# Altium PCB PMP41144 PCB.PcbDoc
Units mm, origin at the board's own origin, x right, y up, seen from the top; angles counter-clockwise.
Board outline 56.79 x 28.91 mm, 6 copper layers (Top Layer 1, Layer 1, Top Layer, Bottom Layer, Layer 2, Bottom Layer 1), stack 1.025 mm thick; 53 components, 24 nets, 115 pads, 67 vias.
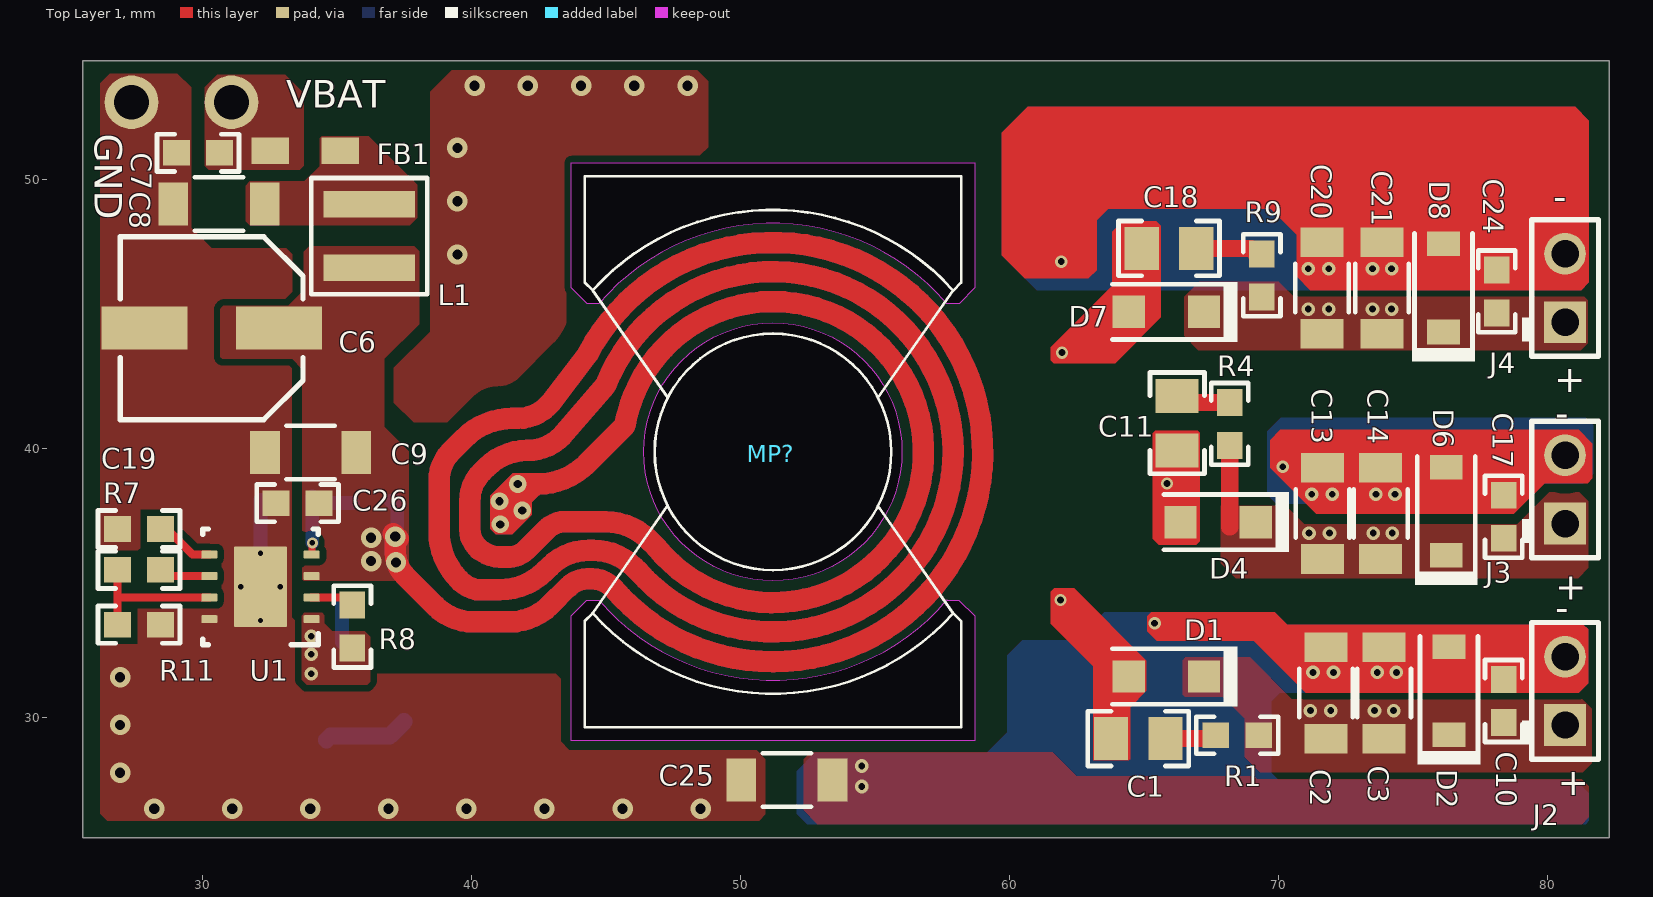
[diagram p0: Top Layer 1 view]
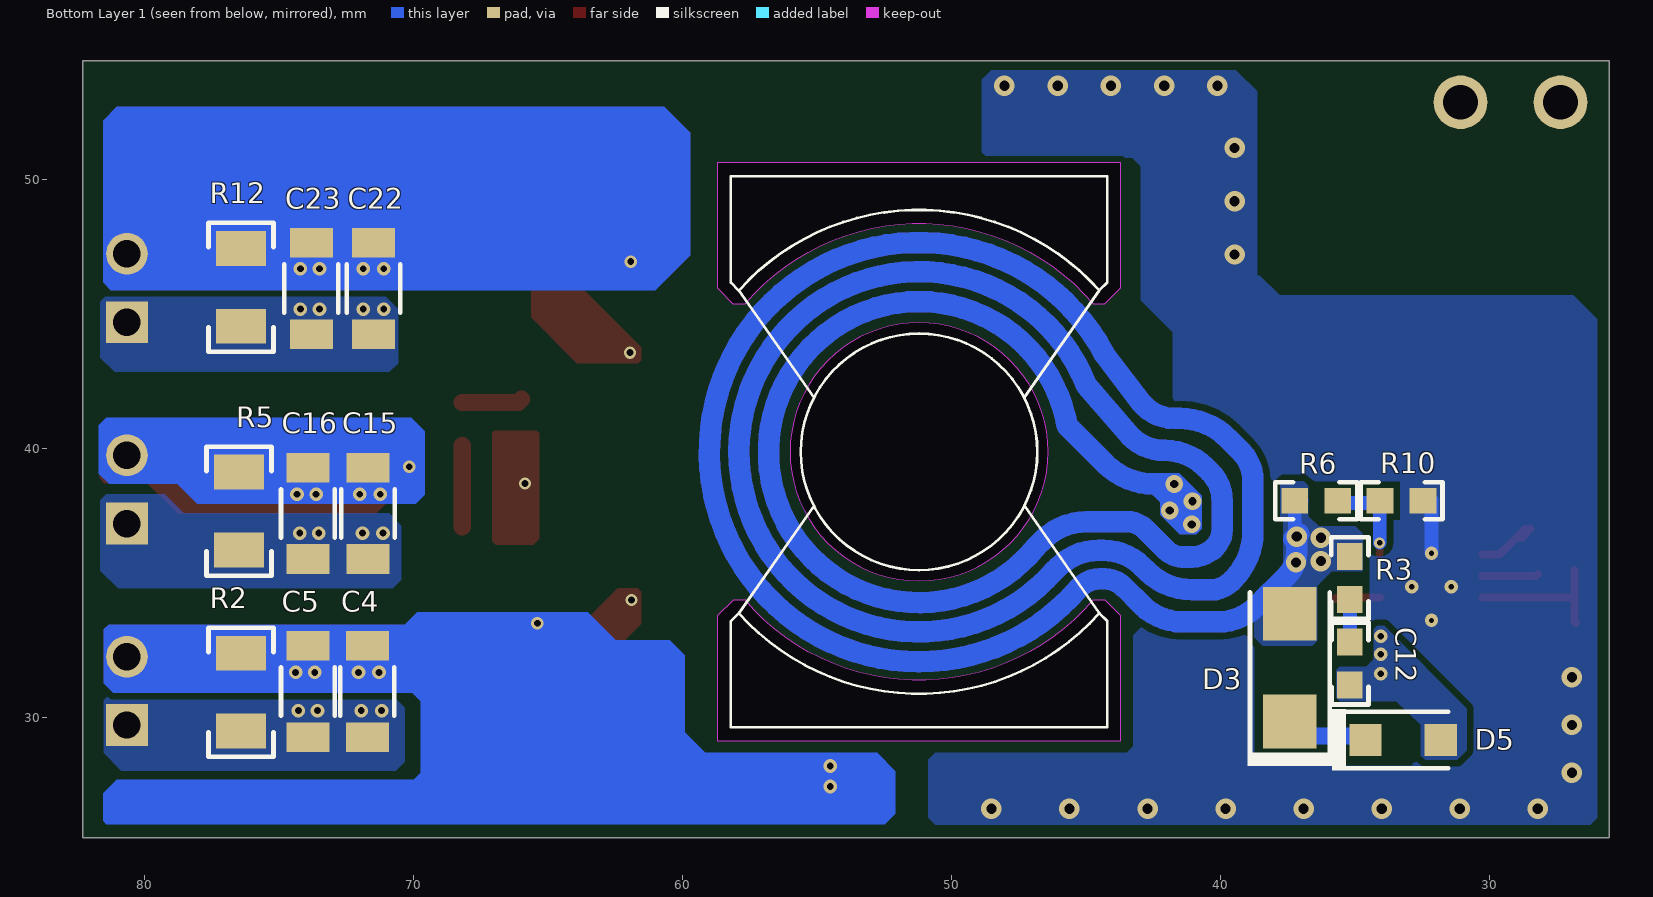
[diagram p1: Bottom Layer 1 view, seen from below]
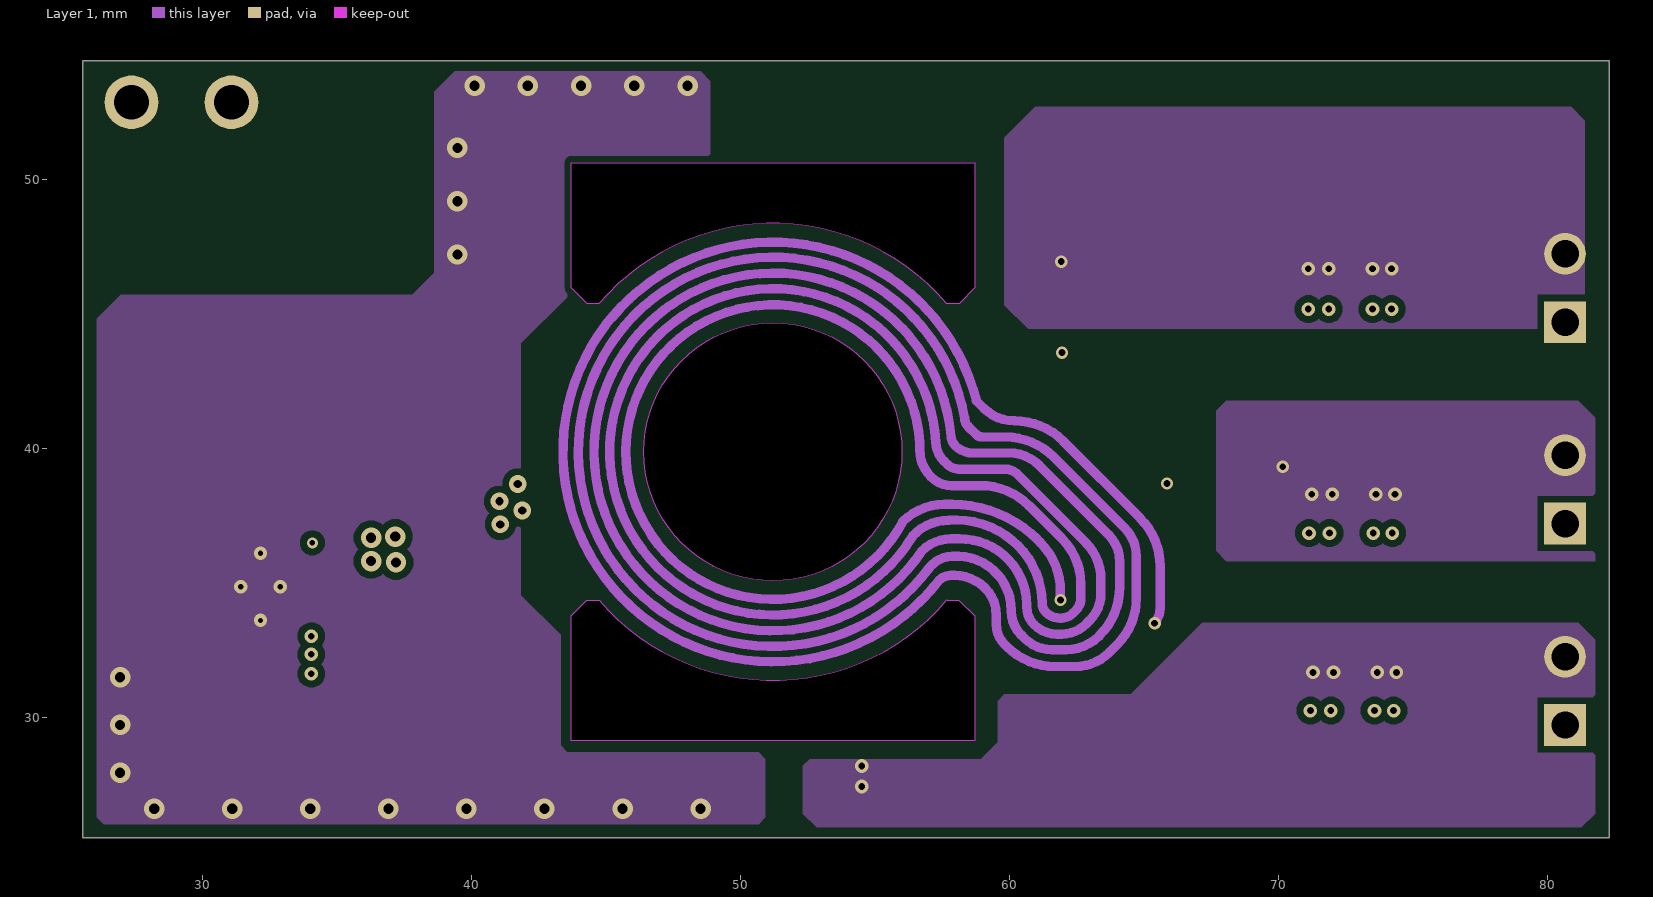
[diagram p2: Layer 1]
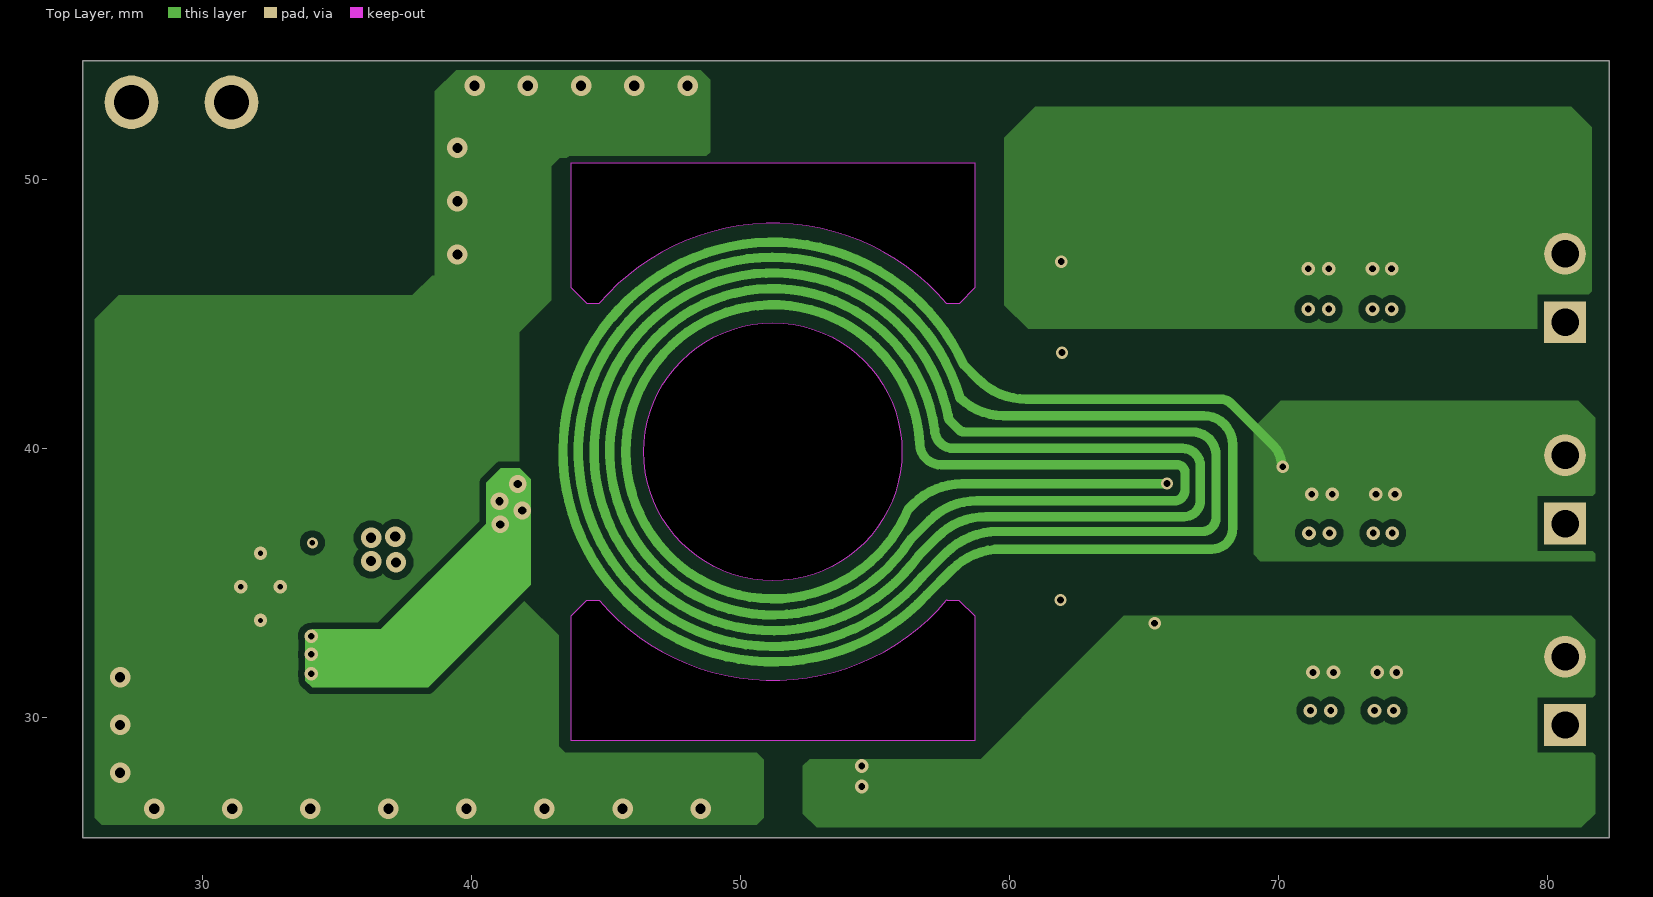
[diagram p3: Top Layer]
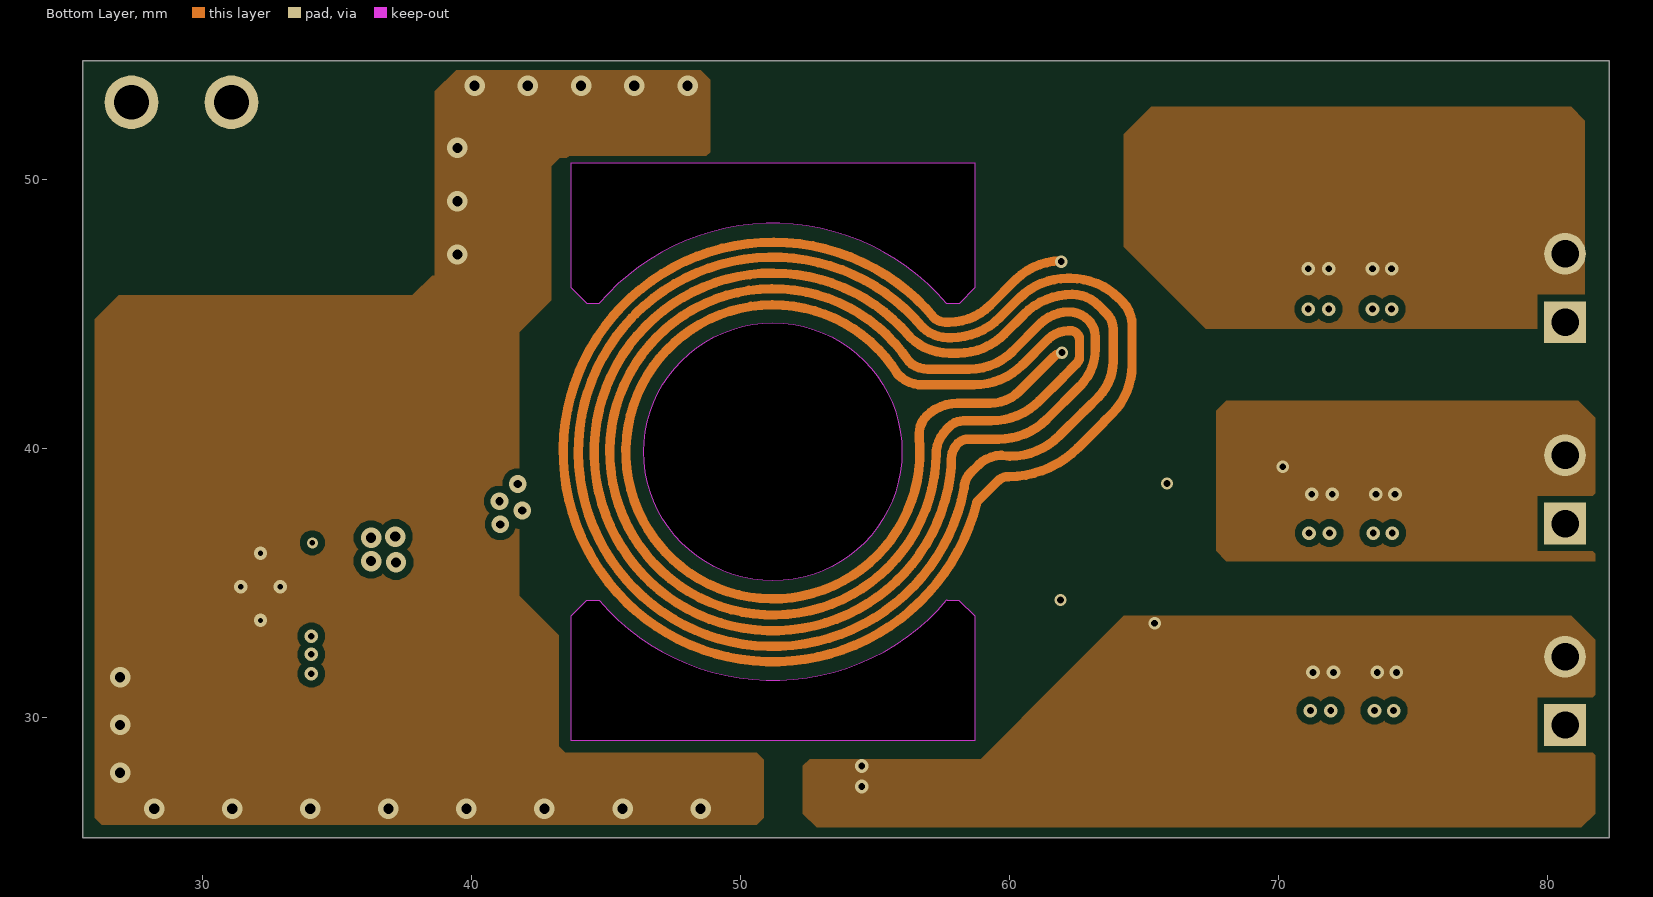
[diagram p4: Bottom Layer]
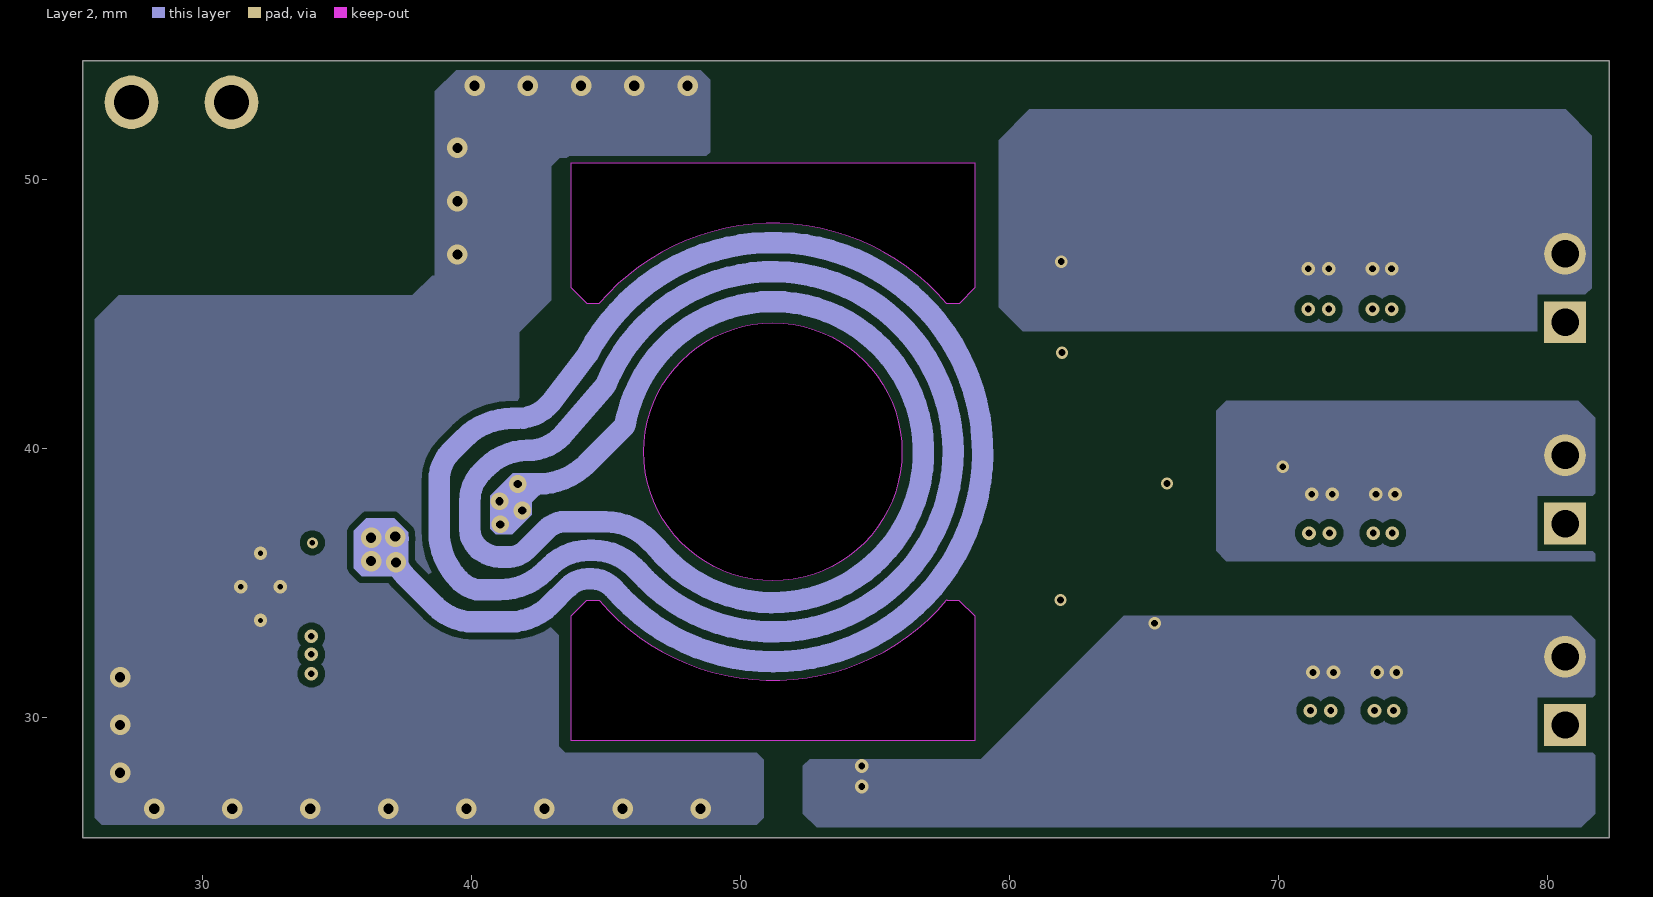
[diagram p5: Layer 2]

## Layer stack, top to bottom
Top Solder: solder mask 0.0102, Solder Resist, Dk 3.5
Top Layer 1: signal copper 0.07
Dielectric 2: prepreg 0.0711, PP-006, Dk 4.1
Layer 1: signal copper 0.07
Dielectric 3: prepreg 0.0711, PP-006, Dk 4.1
Top Layer: signal copper 0.07
Dielectric 1: dielectric 0.32, FR-4, Dk 4.8
Bottom Layer: signal copper 0.07
Dielectric 4: prepreg 0.0711, PP-006, Dk 4.1
Layer 2: signal copper 0.07
Dielectric 5: prepreg 0.0711, PP-006, Dk 4.1
Bottom Layer 1: signal copper 0.07
Bottom Solder: solder mask 0.0102, Solder Resist, Dk 3.5

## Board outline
25.527,25.527 82.321,25.527 82.321,54.432 25.527,54.432
cut-out: 43.706,29.128 43.706,33.778 44.29,34.364 44.298,34.366 44.729,34.366 44.74,34.361 ccw(c51.206,39.878) 57.68,34.369 57.683,34.366 58.115,34.366 58.706,33.778 58.706,29.128
cut-out: 51.206,35.078 cw(c51.206,39.878) 46.406,39.878 cw(c51.206,39.878) 51.206,44.678 cw(c51.206,39.878) 56.006,39.878 cw(c51.206,39.878)
cut-out: 43.706,29.128 43.706,33.778 44.29,34.364 44.298,34.366 44.729,34.366 44.74,34.361 ccw(c51.206,39.878) 57.68,34.369 57.683,34.366 58.115,34.366 58.706,33.778 58.706,29.128
cut-out: 51.206,35.078 cw(c51.206,39.878) 46.406,39.878 cw(c51.206,39.878) 51.206,44.678 cw(c51.206,39.878) 56.006,39.878 cw(c51.206,39.878)
cut-out: 51.206,35.078 cw(c51.206,39.878) 46.406,39.878 cw(c51.206,39.878) 51.206,44.678 cw(c51.206,39.878) 56.006,39.878 cw(c51.206,39.878)
cut-out: 43.706,29.128 43.706,33.778 44.29,34.364 44.298,34.366 44.729,34.366 44.74,34.361 ccw(c51.206,39.878) 57.68,34.369 57.683,34.366 58.115,34.366 58.706,33.778 58.706,29.128
cut-out: 44.298,45.392 43.706,45.978 43.706,50.628 58.706,50.628 58.706,45.978 58.13,45.392 58.115,45.39 57.683,45.39 57.678,45.389 ccw(c51.206,39.878) 44.736,45.39 44.729,45.39

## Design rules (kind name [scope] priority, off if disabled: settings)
AcuteAngle [All] p1: minimum=4.50000000000000E+0001 checktracksonly=FALSE
AssemblyTestPointUsage [All] p1: valid=2
Clearance Clearance_BoardEdge_MountingHoles [OnCopper and InComponentClass('Mounting Holes') vs IsKeepOut] p1: gap=1.016 ignorepadtopadclearanceinfootprint=FALSE except(0: Arc-Hole Track-Hole SMDPad-Hole THPad-Hole Via-Hole Fill-Hole Poly-Hole Region-Hole Text-Hole)
Clearance Clearance_BoardEdge_Poly [OnCopper and InPoly vs IsKeepOut] p2: gap=0.635 ignorepadtopadclearanceinfootprint=FALSE except(0: Arc-Hole Track-Hole SMDPad-Hole THPad-Hole Via-Hole Fill-Hole Poly-Hole Region-Hole Text-Hole)
Clearance Clearance_BoardEdge [OnCopper and Not InComponentClass('Logo') and not InComponentClass('FiducialMark') and not InRegion(1000,500,4000,800) and Not IsKeepout vs IsKeepOut] p3: gap=0.127 ignorepadtopadclearanceinfootprint=FALSE except(0: Arc-Hole Track-Hole SMDPad-Hole THPad-Hole Via-Hole Fill-Hole Poly-Hole Region-Hole Text-Hole)
Clearance Clearance_Poly [InPolygon] p4: gap=0.254 ignorepadtopadclearanceinfootprint=FALSE except(0: Arc-Hole Track-Hole SMDPad-Hole THPad-Hole Via-Hole Fill-Hole Poly-Hole Region-Hole Text-Hole)
Clearance [All] p5: gap=0.203 ignorepadtopadclearanceinfootprint=FALSE except(0: Arc-Hole Track-Hole SMDPad-Hole THPad-Hole Via-Hole Fill-Hole Poly-Hole Region-Hole Text-Hole)
ComponentClearance ComponentClearance_Logo [All] p1: gap=0.254 collisioncheckmode=3 verticalgap=0.254 showdistances=TRUE
ComponentClearance ComponentClearance_ScrewToNut [(HasFootprint('NY PMS 440 0025 PH')) vs (HasFootprint('Keystone_1902C'))] p2: gap=0.127 collisioncheckmode=3 verticalgap=0.254 showdistances=FALSE
ComponentClearance ComponentClearance_MountingHoles [InComponentClass('Mounting Holes')] p3: gap=0.254 collisioncheckmode=3 verticalgap=2540 showdistances=FALSE
ComponentClearance ComponentClearance_SmallPassives [HasFootprint('0201*') or HasFootprint('0402*') or HasFootprint('0508') or HasFootprint('0603*') or HasFootprint('0612') or HasFootprint('0805*') or HasFootprint('0815*') or HasFootprint('0830*') or HasFootprint('1206*') or HasFootprint('1210*') or HasFootprint('1808*') or HasFootprint('1812*') or HasFootprint('1825*') or HasFootprint('2010*') or HasFootprint('2220*') or HasFootprint('2225*') or HasFootprint('2512*') or HasFootprint('2728*') or HasFootprint('3518*') vs HasFootprint('0201*') or HasFootprint('0402*') or HasFootprint('0508') or HasFootprint('0603*') or HasFootprint('0612') or HasFootprint('0805*') or HasFootprint('0815*') or HasFootprint('0830*') or HasFootprint('1206*') or HasFootprint('1210*') or HasFootprint('1808*') or HasFootprint('1812*') or HasFootprint('1825*') or HasFootprint('2010*') or HasFootprint('2220*') or HasFootprint('2225*') or HasFootprint('2512*') or HasFootprint('2728*') or HasFootprint('3518*')] p4: gap=0.254 collisioncheckmode=3 verticalgap=0.254 showdistances=FALSE
ComponentClearance ComponentClearance_THtoSMT [IsThruComponent vs IsSMTComponent] p5: gap=0.254 collisioncheckmode=3 verticalgap=2540 showdistances=FALSE
ComponentClearance ComponentClearance_THtoTH [IsThruComponent vs IsThruComponent] p6: gap=0.254 collisioncheckmode=3 verticalgap=2540 showdistances=FALSE
ComponentClearance [All] p7: gap=0.254 collisioncheckmode=3 verticalgap=0.254 showdistances=FALSE
DiffPairsRouting [All] p1: maxlimit=2.54 minlimit=0.254 mostfreqgap=0.254 toplayer_minwidth=0.381 toplayer_maxwidth=0.381 toplayer_prefwidth=0.381 midlayer1_minwidth=0.381 midlayer1_maxwidth=0.381 midlayer1_prefwidth=0.381 midlayer2_minwidth=0.381 midlayer2_maxwidth=0.381 midlayer2_prefwidth=0.381 midlayer3_minwidth=0.381 midlayer3_maxwidth=0.381 midlayer3_prefwidth=0.381 midlayer4_minwidth=0.381 midlayer4_maxwidth=0.381 midlayer4_prefwidth=0.381 bottomlayer_minwidth=0.381 bottomlayer_maxwidth=0.381 bottomlayer_prefwidth=0.381 maxuncoupledlength=25.4
FabricationTestPointUsage TestPointUsage [All] p1: valid=2 allowmultiple=FALSE
FabricationTestpoint Testpoint [All] p1: side=3 testpointundercomponent=TRUE minsize=1.016 maxsize=2.54 preferedsize=1.524 minholesize=0 maxholesize=1.016 preferedholesize=0.813 testpointgrid=0.025 allowsidetop=TRUE allowsidebottom=TRUE usegrid=TRUE gridtolerance=0
FanoutControl Fanout_LCC [IsLCC] p1: bgadir=Out bgaviamode=Centered fanoutstyle=Auto fanoutdirection=Alternating viagrid=0.025 // Fanout_LCC (Default Rule)
FanoutControl Fanout_BGA [IsBGA] p2: bgadir=Out bgaviamode=Centered fanoutstyle=Auto fanoutdirection=Alternating viagrid=0.025 // Fanout_BGA (Default Rule)
FanoutControl Fanout_Default [All] p4: bgadir=Out bgaviamode=Centered fanoutstyle=Auto fanoutdirection=Alternating viagrid=0.025 // Fanout_Default (Default Rule)
FanoutControl Fanout_Small [(CompPinCount < 5)] p5: bgadir=Out bgaviamode=Centered fanoutstyle=Auto fanoutdirection=OutThenIn viagrid=0.025 // Fanout_Small (Default Rule)
HoleSize [All] p1: absolutevalues=TRUE maxlimit=6.375 minlimit=0.152 maxpercent=80.000 minpercent=20.000
MinimumAnnularRing [All] p1: minimumring=0.076
MinimumSolderMaskSliver MinimumSolderMaskSliver_Logo [InComponentClass('Logo') vs InComponentClass('Logo')] p1: minsoldermaskwidth=0.018
MinimumSolderMaskSliver [All] p2: minsoldermaskwidth=0
PlaneConnect [All] p1: planeconnectstyle=Direct reliefexpansion=0.254 reliefentries=4 reliefconductorwidth=0.254 reliefairgap=0.254
PolygonConnect [All] p1: connectstyle=Direct reliefconductorwidth=0.254 reliefentries=4 polygonreliefangle="90 Angle" airgapwidth=0.254
RoutingCorners [All] p1: cornerstyle=45-Degree minsetback=0.254 maxsetback=2.54
RoutingVias [All] p1: holewidth=0.406 width=0.864 viastyle="Through Hole" minholewidth=0.203 minwidth=0.406 maxholewidth=1.016 maxwidth=1.651
SMDToCorner [All] p1: distance=0
SilkToSilkClearance [All] p1: silktosilkclearance=0
SilkToSolderMaskClearance SilkscreenOverComponentPads [IsPad] p1: minsilkscreentomaskgap=0 clearancetoexposedcopper=TRUE
SolderMaskExpansion [All] p1: expansion=0.076 istentingtop=FALSE
Width [All] p1: maxlimit=2.54 minlimit=0.152 preferedwidth=0.254 checkconnectedcopper=TRUE
15 further rules are at their usual default settings.

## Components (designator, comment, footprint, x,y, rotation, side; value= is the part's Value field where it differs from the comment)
C1 "GRM21A5C2E220JW01D" 0805_HV 64.795,29.21 r180 top value=22pF
C2 "CGA5L1X7R1H106K160AC" 1206_190 71.78,30.91 r90 top value=10uF
C3 "CGA5L1X7R1H106K160AC" 1206_190 73.939,30.91 r90 top value=10uF
C4 "CGA5L3X7R1H475K160AE" 1206_190 71.73,30.963 r90 bottom value=4.7uF
C5 "CGA5L3X7R1H475K160AE" 1206_190 73.939,30.963 r90 bottom value=4.7uF
C6 "EEH-ZC1H220P" Panasonic_D 30.328,44.475 r180 top value=22uF
C7 "C0603C104K5RACAUTO" 0603 29.82,51.003 r180 top value=0.1uF
C8 "CGA5L1X7R1H106K160AC" 1206_190 30.607,49.098 r180 top value=10uF
C9 "CGA5L1X7R1H106K160AC" 1206_190 34.012,39.853 r180 top value=10uF
C10 "C0603C104K5RACAUTO" 0603 78.384,30.607 r90 top value=0.1uF
C11 "GRM21A5C2E220JW01D" 0805_HV 66.243,40.945 r270 top value=22pF
C12 "GRM1885C2A220JA01D" 0603 35.179,32.004 r270 bottom value=22pF
C13 "CGA5L1X7R1H106K160AC" 1206_190 71.653,37.592 r90 top value=10uF
C14 "CGA5L1X7R1H106K160AC" 1206_190 73.812,37.592 r90 top value=10uF
C15 "CGA5L3X7R1H475K160AE" 1206_190 71.704,37.592 r90 bottom value=4.7uF
C16 "CGA5L3X7R1H475K160AE" 1206_190 73.939,37.592 r90 bottom value=4.7uF
C17 "C0603C104K5RACAUTO" 0603 78.384,37.465 r90 top value=0.1uF
C18 "GRM21A5C2E220JW01D" 0805_HV 65.938,47.447 r180 top value=22pF
C19 "GCM188R71E473KA37D" 0603 27.625,37.008 r180 top value=0.047uF
C20 "CGA5L1X7R1H106K160AC" 1206_190 71.628,45.974 r90 top value=10uF
C21 "CGA5L1X7R1H106K160AC" 1206_190 73.863,45.974 r90 top value=10uF
C22 "CGA5L3X7R1H475K160AE" 1206_190 71.501,45.949 r90 bottom value=4.7uF
C23 "CGA5L3X7R1H475K160AE" 1206_190 73.812,45.949 r90 bottom value=4.7uF
C24 "C0603C104K5RACAUTO" 0603 78.13,45.847 r90 top value=0.1uF
C25 "202R18W102KV4E" 1206_190 51.722,27.673 r180 top value=1000pF
C26 "C0603C104K5RACAUTO" 0603 33.528,37.973 r180 top value=0.1uF
D1 "STPS2H100ZFY" SOD-123F 65.837,31.521 r180 top value=100V
D2 "MMSZ4710-HE3-08" SOD-123 76.352,30.988 r90 top value=25V
D3 "3SMAJ5932B-TP" SMA 37.414,31.852 r90 bottom value=20V
D4 "STPS2H100ZFY" SOD-123F 67.764,37.262 r180 top value=100V
D5 "PMEG60T30ELRX" SOD-123W 33.198,29.159 r180 bottom value=60V
D6 "MMSZ4710-HE3-08" SOD-123 76.251,37.668 r90 top value=25V
D7 "STPS2H100ZFY" SOD-123F 65.837,45.085 r180 top value=100V
D8 "MMSZ4710-HE3-08" SOD-123 76.149,45.974 r90 top value=25V
FB1 "782853611" WE-CBA_0805_L2W1.2H0.9_HC 33.807,51.079 r0 top
J2 "HTSW-102-09-G-S" Samtec_HTSW-102-09-x-S 80.67,30.988 r90 top
J3 "HTSW-102-09-G-S" Samtec_HTSW-102-09-x-S 80.67,38.481 r90 top
J4 "HTSW-102-09-G-S" Samtec_HTSW-102-09-x-S 80.67,45.974 r90 top
L1 "XFL4030-472MEB" XFL4030 36.195,47.904 r270 top value=4.7uH
MP? "PC95PQI20/9Z-12" FP-PC95PQI20/9Z-12_FERRITE_CORE-MFG 51.13,39.802 r0 top
R1 "CRCW0603100RFKEA" 0603 68.478,29.337 r180 top value=100
R2 "CRCW120610K0FKEAHP" 1206 76.429,30.937 r270 bottom value=10.0k
R3 "CRCW0603100RFKEA" 0603 35.179,35.179 r90 bottom value=100
R4 "CRCW0603100RFKEA" 0603 68.199,40.919 r90 top value=100
R5 "CRCW120610K0FKEAHP" 1206 76.505,37.67 r270 bottom value=10.0k
R6 "CRCW060363K4FKEA" 0603 36.431,38.059 r0 bottom value=63.4k
R7 "CRCW0603261KFKEA" 0603 27.625,35.484 r0 top value=261k
R8 "CRCW0603127KFKEA" 0603 35.56,33.376 r90 top value=127k
R9 "CRCW0603100RFKEA" 0603 69.393,46.444 r90 top value=100
R10 "CRCW060323K7FKEA" 0603 33.256,38.059 r0 bottom value=23.7k
R11 "CRCW060312K1FKEA" 0603 27.625,33.452 r180 top value=12.1k
R12 "CRCW120610K0FKEAHP" 1206 76.429,45.999 r270 bottom value=10.0k
U1 "LM25184QNGURQ1" NGU0008C 32.146,34.856 r180 top

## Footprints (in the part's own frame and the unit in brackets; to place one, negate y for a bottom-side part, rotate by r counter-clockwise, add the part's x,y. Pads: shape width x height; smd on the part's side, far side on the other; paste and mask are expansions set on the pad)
0603 [mm] "0603 from SM-752 data"
  rect 1x0.95 smd: 1(-0.8,0) 2(0.8,0)
  silkscreen extent -1.52,-0.69 1.52,0.69, body extent -0.87,-0.47 0.87,0.47, height 1
0805_HV [mil] "0805 with 30mil clearance between pads"
  rect 50x63 smd: 1(-40,0) 2(40,0)
  silkscreen extent -74,-40 74,40, body extent -43,-29 43,29, height 57
1206 [mm] "1206 from SM-752 data"
  rect 1.3x1.85 smd: 1(-1.45,0) 2(1.45,0)
  silkscreen extent -2.4,-1.21 2.4,1.21, body extent -1.7,-0.9 1.7,0.9, height 1.35
1206_190 [mm] "1206_190"
  rect 1.1x1.6 smd: 1(-1.7,0) 2(1.7,0)
  silkscreen extent -0.9,-1 0.9,1, body extent -1.75,-0.95 1.75,0.95, height 1.9
FP-PC95PQI20/9Z-12_FERRITE_CORE-MFG [mm] "Recommended Land Pattern"
  body extent -7.3,-10.55 7.3,10.55, height 0.25
NGU0008C [mm] "SON, 8-Leads, Body 4x4mm, Pitch 0.8mm"
  rrect33% 0.6x0.3 smd: 1(-1.9,1.2) 2(-1.9,0.4) 3(-1.9,-0.4) 4(-1.9,-1.2) 5(1.9,-1.2) 6(1.9,-0.4) 7(1.9,0.4) 8(1.9,1.2)
  rrect8% 1.75x1.31 on Top Paste: 9(0,0.755) 9(0,-0.755)
  rrect5% 1.98x3 smd paste-1.5: 9(0,0)
  silkscreen extent -2.15,-2.15 2.15,2.15, body extent -2,-2 2,2, height 0.77
Panasonic_D [mm] "SMD, 2-Leads, Dia 6.3mm"
  rect 3.2x1.6 smd: 1(-2.5,0) 2(2.5,0)
  silkscreen extent -3.4,-3.4 3.4,3.4, body extent -3.4,-3.4 3.4,3.4, height 6.11
Samtec_HTSW-102-09-x-S [mm] "Header, 2x1, 2.54mm, TH"
  rect 1.55x1.55 hole 1.02: 1(-1.27,0)
  round 1.55 hole 1.02: 2(1.27,0)
  silkscreen extent -2.54,-1.24 2.54,1.6, body extent -2.54,-1.24 2.54,1.24, height 8.38
SMA [mm] "Molded Diode, 2-Leads, Body 4.3x2.6mm, IPC Medium Density, based on OnSemi component dimensions and land pattern"
  rect 2x2 smd: 1(-2,0) 2(2,0)
  silkscreen extent -3.66,-1.57 2.79,1.57, body extent -2.6,-1.3 2.6,1.3, height 2.42
SOD-123 [mm] "On Semi recommended land pattern"
  rect 0.915x1.22 smd: 1(-1.637,0) 2(1.637,0)
  silkscreen extent -2.74,-1.17 2.03,1.17, body extent -1.93,-0.9 1.93,0.9, height 1.35
SOD-123F [mm] "NXP recommended land pattern"
  rect 1.2x1.2 smd paste-0.05: 1(-1.4,0) 2(1.4,0)
  silkscreen extent -2.64,-1.12 2.01,1.12, body extent -1.8,-0.85 1.8,0.85, height 1.2
SOD-123W [mm] "NXP recommended land pattern"
  rect 1.2x1.2 smd paste-0.05: 1(-1.4,0) 2(1.4,0)
  silkscreen extent -2.64,-1.14 1.68,1.15, body extent -1.85,-0.95 1.85,0.95, height 1.1
WE-CBA_0805_L2W1.2H0.9_HC [mm] "SMD EMI Suppression Ferrite Bead, 2-Leads, body 2.00x1.20mm"
  rect 1.4x1 smd: 1(-1.3,0) 2(1.3,0)
  body extent -1,-0.6 1,0.6, height 0.9
XFL4030 [mm] "Coilcraft XFL4030"
  rect 0.98x3.4 smd: 1(-1.185,0) 2(1.185,0)
  silkscreen extent -2.16,-2.16 2.16,2.16, body extent -2.15,-2.15 2.15,2.15, height 3.1

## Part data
C1 C11 C18: library part CMP-0008240-1, "CAP, CERM, 22 pF, 250 V, +/- 5%, C0G/NP0, 0805", Cap_Case=0805, Manufacturer=MuRata, Supplier Part Number 1=490-5534-1-ND, TempCo=C0G/NP0, Tolerance_%=5%, Value1=Unknown, Value2=250V, ValueDisplayed=22pF
C2 C3 C8 C9 C13 C14 C20 C21: library part CMP-0085950-1, "CAP, CERM, 10 µF, 50 V,+/- 10%, X7R, AEC-Q200 Grade 1, 1206", Cap_Case=1206, Manufacturer=TDK, TempCo=X7R, Tolerance_%=10%, Value2=50V, ValueDisplayed=10µF
C4 C5 C15 C16 C22 C23: library part CMP-0085349-1, "CAP, CERM, 4.7 µF, 50 V,+/- 10%, X7R, AEC-Q200 Grade 1, 1206", Cap_Case=1206, Manufacturer=TDK, TempCo=X7R, Tolerance_%=10%, Value2=50V, ValueDisplayed=4.7µF
C6: library part CMP-0012597-3, "CAP, Polymer Hybrid, 22 uF, 50 V, +/- 20%, 0.08 ohm, AEC-Q200 Grade 1, D6.3xL5.8mm SMD", Cap_Case=6.3x5.8, Manufacturer=Panasonic, Supplier Part Number 1=P15463CT-ND, Tolerance_%=20%, Value1="0.08 ohm", Value2=50V, ValueDisplayed=22uF
C7 C10 C17 C24 C26: library part CMP-0079602-1, "CAP, CERM, 0.1 µF, 50 V,+/- 10%, X7R, AEC-Q200 Grade 1, 0603", Cap_Case=0603, Manufacturer=Kemet, Supplier Part Number 1=399-6856-1-ND, TempCo=X7R, Tolerance_%=10%, Value2=50V, ValueDisplayed=0.1µF
C12: library part CMP-0007255-4, "CAP, CERM, 22 pF, 100 V, +/- 5%, C0G/NP0, 0603", Cap_Case=0603, Manufacturer=MuRata, Supplier Part Number 1=490-1335-1-ND, TempCo=C0G/NP0, Tolerance_%=5%, Value1=Unknown, Value2=100V, ValueDisplayed=22pF
C19: library part CMP-0007141-3, "CAP, CERM, 0.047 uF, 25 V, +/- 10%, X7R, AEC-Q200 Grade 1, 0603", Cap_Case=0603, Manufacturer=MuRata, Supplier Part Number 1=490-8018-1-ND, TempCo=X7R, Tolerance_%=10%, Value1=Unknown, Value2=25V, ValueDisplayed=0.047uF
C25: library part CMP-0008572-2, "CAP, CERM, 1000 pF, 2000 V, +/- 10%, X7R, 1206_190", Cap_Case=1206, Manufacturer="Johanson Technology", TempCo=X7R, Tolerance_%=10%, Value1=Unknown, Value2=2000V, ValueDisplayed=1000pF
D1 D4 D7: library part CMP-0080011-2, "Diode, Schottky, 100 V, 2 A, AEC-Q101, SOD-123F", Manufacturer=STMicroelectronics, Value1=2A, Value2=0.5V
D2 D6 D8: library part CMP-0077583-1, "Diode, Zener, 25 V, 500 mW, AEC-Q101, SOD-123", Manufacturer=Vishay-Semiconductor, Power_W=500mW, Supplier Part Number 1=MMSZ4710-HE3-08-ND, Value1=0.5W
D3: library part CMP-0005511-4, "Diode, Zener, 20 V, 3 W, SMA", Manufacturer="Micro Commercial Components", Power_W=3W
D5: library part CMP-0085903-1, "Diode, Schottky, 60 V, 3 A, AEC-Q101, SOD-123W", Manufacturer=Nexperia, Value1=3A, Value2=0.62V
FB1: library part CMP-0066722-1, "WE-CBA SMT EMI Suppression Ferrite Bead, size 0805, 600Ohm, 2A", Case/Size Code=0805, DC Resistance Max=0.11Ohm, Manufacturer="Wurth Elektronik", Operating Temperature Max=125°C, Operating Temperature Min=-55°C, Rated Current=2A
J2 J3 J4: library part CMP-0075626-1, "Header, 100mil, 2x1, Gold, TH", Color=Black, Manufacturer=Samtec
L1: library part CMP-0061153-1, "Inductor, Shielded, Composite, 4.7 uH, 2.1 A, 0.03 ohm, SMD", Manufacturer=Coilcraft, Value1="0.03 ohm", Value2=2.1A, ValueDisplayed=4.7uH
MP?: library part CMP-0124779-1, Digikey Part Number=445-180872-ND, Manufacturer=TDK, Mouser Part Number=810-PC95PQI20/9Z-12, Operating Temperature Range=to
R1 R3 R4 R9: library part CMP-0021991-4, "RES, 100, 1%, 0.1 W, AEC-Q200 Grade 0, 0603", Manufacturer=Vishay-Dale, Power_W=100mW, Supplier Part Number 1=541-100HCT-ND, TempCo="100 ppm/C", Tolerance_%=1%, Value2=0.1W, Value_Code=100R, ValueDisplayed=100
R2 R5 R12: library part CMP-0016578-1, "RES, 10.0 k, 1%, 0.5 W, 1206", Manufacturer=Vishay-Dale, Power_W=500mW, Supplier Part Number 1=541-10.0KUCT-ND, TempCo="100 ppm/C", Tolerance_%=1%, Value2=0.5W, Value_Code=10k0, ValueDisplayed=10.0k
R6: library part CMP-0022540-4, "RES, 63.4 k, 1%, 0.1 W, AEC-Q200 Grade 0, 0603", Manufacturer=Vishay-Dale, Power_W=100mW, Supplier Part Number 1=541-63.4KHCT-ND, TempCo="100 ppm/C", Tolerance_%=1%, Value2=0.1W, Value_Code=63k4, ValueDisplayed=63.4k
R7: library part CMP-0022244-4, "RES, 261 k, 1%, 0.1 W, AEC-Q200 Grade 0, 0603", Manufacturer=Vishay-Dale, Power_W=100mW, Supplier Part Number 1=541-261KHCT-ND, TempCo="100 ppm/C", Tolerance_%=1%, Value2=0.1W, Value_Code=261k
R8: library part CMP-0022028-4, "RES, 127 k, 1%, 0.1 W, AEC-Q200 Grade 0, 0603", Manufacturer=Vishay-Dale, Power_W=100mW, Supplier Part Number 1=541-127KHCT-ND, TempCo="100 ppm/C", Tolerance_%=1%, Value2=0.1W, Value_Code=127k
R10: library part CMP-0022229-4, "RES, 23.7 k, 1%, 0.1 W, AEC-Q200 Grade 0, 0603", Manufacturer=Vishay-Dale, Power_W=100mW, Supplier Part Number 1=541-23.7KHCT-ND, TempCo="100 ppm/C", Tolerance_%=1%, Value2=0.1W, Value_Code=23k7, ValueDisplayed=23.7k
R11: library part CMP-0022030-4, "RES, 12.1 k, 1%, 0.1 W, AEC-Q200 Grade 0, 0603", Manufacturer=Vishay-Dale, Power_W=100mW, Supplier Part Number 1=541-12.1KHCT-ND, TempCo="100 ppm/C", Tolerance_%=1%, Value2=0.1W, Value_Code=12k1, ValueDisplayed=12.1k
U1: library part CMP-0860959-2, "42-VIN PSR Flyback DC/DC Converter with 65-V, 4-A Integrated MOSFET, NGU0008C (WSON-8)", Alternate Manufacturer="Texas Instruments"

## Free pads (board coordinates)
  round 2 hole 1.3: 1(27.348,52.882) 1(31.064,52.882)

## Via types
v1: diameter 0.508, hole 0.254, Top Layer 1 to Bottom Layer 1, 29 vias
v2: diameter 0.762, hole 0.381, Top Layer 1 to Bottom Layer 1, 23 vias
v3: diameter 0.457, hole 0.254, Top Layer 1 to Bottom Layer 1, 6 vias
v4: diameter 0.66, hole 0.305, Top Layer 1 to Bottom Layer 1, 4 vias
v5: diameter 0.5, hole 0.2, Top Layer 1 to Bottom Layer 1, 4 vias
v6: diameter 0.406, hole 0.203, Top Layer 1 to Bottom Layer 1, 1 vias

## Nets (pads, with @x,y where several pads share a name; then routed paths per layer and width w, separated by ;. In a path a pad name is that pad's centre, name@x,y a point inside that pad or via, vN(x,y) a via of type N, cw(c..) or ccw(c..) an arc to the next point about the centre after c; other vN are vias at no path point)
EN: R6.1 R10.2 U1.4 | length 3.7
  Top Layer 1 w0.254: v6(34.074,36.492) 34.06,36.478 34.06,36.079 U1.4@34.097,36.079
  Bottom Layer 1 w0.508: v6(34.074,36.492) R10.2@34.074,38.214 ; R10.2@34.074,37.96 34.061,37.973 R6.1@35.585,37.973
FB: R8.2 U1.2 | length 1.7
  Top Layer 1 w0.305: U1.2 35.674,34.456 R8.2@35.712,34.417
GND1: C2.2 C3.2 C4.2 C5.2 C10.2 C25.1 D2.2 J2.2 R2.1 | length 287.1
  Layer 1 w0.35: 45.209,44.865 cw(c51.206,39.878) 58.771,41.781 ; 45.601,45.317 ccw(c51.206,39.878) 57.383,35.098 cw(c57.831,34.65) 57.831,35.283 57.97,35.283 cw(c57.97,33.707) 59.085,34.822 ; 46.087,44.997 cw(c51.206,39.878) 58.336,41.137 ; 46.299,45.201 ccw(c51.206,39.878) 57.049,35.602 ; 46.348,44.419 cw(c51.206,39.878) 57.83,40.466 ; 46.626,43.861 cw(c51.206,39.878) 57.266,40.236 ; 46.688,36.766 ccw(c51.206,39.878) 56.042,37.285 ; 46.881,36.53 cw(c51.206,39.878) 56.666,40.21 ; 47.178,45.175 ccw(c51.206,39.878) 56.746,36.191 ; 48.047,45.061 ccw(c51.206,39.878) 56.411,36.754 cw(c57.744,35.51) 57.744,37.333 cw(c58.006,34.059) 60.329,36.381 cw(c58.177,34.232) 61.219,34.235 ; 56.043,37.287 cw(c57.576,35.754) 57.576,37.922 57.878,37.922 cw(c57.88,33.444) 61.046,36.611 ; 56.667,40.208 56.667,39.953 ccw(c58.081,39.953) 57.081,38.953 ; 56.746,36.19 cw(c57.838,35.098) 57.838,36.642 58.123,36.642 ccw(c58.122,36.992) 58.126,36.642 cw(c58.17,34.162) 60.65,34.161 ; 57.048,35.601 57.13,35.682 cw(c57.871,34.941) 57.871,35.989 cw(c58.05,33.974) 60.074,33.974 ; 57.092,38.941 ccw(c57.858,39.707) 57.858,38.623 58.933,38.623 cw(c58.933,36.083) 60.729,37.879 61.958,36.65 cw(c60.258,34.95) 62.662,34.95 62.662,34.437 cw(c62.011,34.437) 62.471,33.978 62.365,33.871 cw(c61.935,34.3) 61.935,33.693 61.87,33.693 cw(c61.87,34.387) 61.379,33.896 ; 57.267,40.236 ccw(c58.23,40.236) 57.549,39.555 57.689,39.415 ccw(c58.123,39.849) 58.123,39.235 59.837,39.235 cw(c59.837,38.568) 60.348,38.997 62.843,36.502 62.843,36.501 cw(c61.485,35.142) 63.406,35.142 63.406,34.63 ; 57.828,40.488 ccw(c58.362,40.488) 57.984,40.11 57.998,40.096 ccw(c58.63,40.728) 58.63,39.835 60.002,39.835 cw(c60.002,38.271) 61.108,39.377 63.698,36.787 cw(c62.716,35.805) 64.105,35.805 64.105,34.844 cw(c61.565,34.844) 63.361,33.048 63.337,33.025 cw(c62.111,34.252) 62.111,32.517 61.586,32.517 cw(c61.586,33.948) 60.574,32.936 60.431,33.079 cw(c61.294,33.942) 60.074,33.942 ; 58.336,41.135 ccw(c51.206,39.878) 58.336,41.137 ; 58.336,41.138 ccw(c58.778,41.138) 58.336,41.137 ; 58.771,41.78 59.051,41.5 ccw(c60.183,42.632) 60.183,41.031 ; 59.085,34.821 59.104,34.802 cw(c58.12,33.818) 59.512,33.825 ; 59.512,33.797 59.512,33.462 ccw(c60.562,33.462) 59.82,32.72 59.904,32.636 ccw(c61.7,34.432) 61.7,31.892 62.449,31.892 ccw(c62.449,33.687) 63.718,32.418 64.011,32.711 ccw(c62.29,34.432) 64.724,34.432 64.724,35.99 ccw(c63.224,35.99) 64.285,37.051 61.651,39.685 ccw(c59.855,37.889) 59.855,40.429 58.998,40.429 cw(c58.998,40.759) 58.766,40.526 58.465,40.826 cw(c58.778,41.138) 58.336,41.137 ; 60.2,41.029 cw(c60.2,38.489) 61.996,40.285 64.867,37.414 cw(c63.071,35.618) 65.611,35.618 65.611,34.061 cw(c64.822,34.061) v3@65.38,33.503 ; 60.65,34.159 60.65,34.161 ; 61.049,36.609 61.156,36.502 cw(c59.36,34.706) 61.9,34.706 v3@61.9,34.392 ; 61.345,33.93 cw(c61.651,34.235) 61.219,34.233 ; 63.406,34.597 cw(c62.026,34.597) 63.002,33.622 62.851,33.471 cw(c61.953,34.368) 61.953,33.099 61.772,33.099 cw(c61.772,34.304) 60.919,33.452 cw(c61.569,34.102) 60.65,34.102 60.65,34.161 ; 59.512,33.825 cw(c58.12,33.818) 59.512,33.818 59.512,33.825 ; 61.219,34.233 cw(c61.651,34.235) 61.219,34.235 ; 61.219,34.233 61.219,34.235
  other v1: 54.508,27.432 54.508,28.194 71.298,31.674 72.06,31.674 73.685,31.674 74.397,31.674
  other v3: 65.405,33.503 61.9,34.366
GND2: C13.2 C14.2 C15.2 C16.2 C17.2 D6.2 J3.2 R5.1 | length 307.4
  Top Layer 1 w0.635: v1(71.247,38.303) 71.298,38.354 C13.2@71.298,39.04 ; v1(72.009,38.303) C13.2@72.009,39.116
  Top Layer w0.35: 45.209,44.865 cw(c51.206,39.878) 58.301,43.119 ; 45.502,44.335 cw(c51.206,39.878) 58.159,41.894 ; 45.812,45.526 ccw(c51.206,39.878) 56.93,34.564 ; 46.257,44.327 cw(c51.206,39.878) 57.721,41.238 ; 46.491,45.372 ccw(c51.206,39.878) 56.779,35.255 ; 46.597,43.828 cw(c51.206,39.878) 57.22,40.709 ; 46.693,36.789 ccw(c51.207,39.878) 56.246,37.749 56.437,37.94 cw(c58.233,36.144) 58.233,38.684 60.942,38.684 ; 46.892,36.516 cw(c51.206,39.878) 56.667,40.194 ccw(c57.465,40.193) 57.465,39.395 66.243,39.395 cw(c66.243,39.106) 66.533,39.106 66.533,38.451 cw(c66.139,38.451) 66.139,38.057 ; 47.089,44.338 ccw(c51.206,39.878) 56.331,36.624 ; 47.152,45.155 ccw(c51.206,39.878) 56.623,36.012 ; 56.33,36.624 57.036,37.331 cw(c58.789,35.578) 58.789,38.057 66.101,38.057 ; 56.622,36.012 57.331,36.721 cw(c59.127,34.925) 59.127,37.465 60.891,37.465 66.5,37.465 ccw(c66.5,38.072) 67.107,38.072 67.107,39.347 ccw(c66.449,39.347) 66.449,40.005 63.932,40.005 60.737,40.005 57.922,40.005 cw(c57.922,40.706) 57.221,40.706 ; 56.777,35.25 57.638,36.111 cw(c59.581,34.168) 59.581,36.916 67.183,36.916 ccw(c67.183,37.419) 67.686,37.419 67.686,39.751 ccw(c66.822,39.751) 66.822,40.615 63.932,40.615 61.334,40.615 60.985,40.615 ; 56.929,34.559 57.872,35.502 cw(c59.704,33.669) 59.704,36.261 67.536,36.261 ccw(c67.536,37.033) 68.308,37.033 68.308,40.145 ccw(c67.229,40.145) 67.229,41.224 63.983,41.224 60.788,41.224 ; 57.716,41.242 ccw(c58.035,41.242) 57.81,41.017 58.115,40.711 ccw(c58.348,40.944) 58.348,40.615 61.333,40.615 ; 58.161,41.892 ccw(c59.774,43.505) 59.774,41.224 60.823,41.224 ; 58.301,43.116 58.839,42.578 ccw(c60.635,44.374) 60.635,41.834 61.123,41.834 ; 60.737,38.684 63.449,38.684 65.76,38.684 ccw(c65.76,38.771) v3@65.822,38.71 ; 60.813,41.834 67.866,41.834 ; 67.785,41.836 cw(c67.785,40.543) 67.866,41.834 ; v3@70.129,39.37 ccw(c69.087,39.37) 69.824,40.107 68.261,41.67 ccw(c67.866,41.275) 67.866,41.834
  other v1: 73.635,38.303 74.346,38.303
  other v3: 65.862,38.697 70.17,39.324
GND3: C20.2 C21.2 C22.2 C23.2 C24.2 D8.2 J4.2 R12.1 | length 269
  Bottom Layer w0.35: 45.107,34.999 ccw(c51.206,39.878) 58.789,38.007 ; 45.402,34.668 cw(c51.206,39.878) 57.199,44.871 ccw(c57.609,45.282) 57.609,44.701 57.77,44.701 ccw(c57.77,46.848) 59.287,45.33 60.241,46.284 cw(c61.915,44.61) v3@61.915,46.977 ; 45.767,36.043 ccw(c51.206,39.878) 57.837,39.31 ; 45.961,44.868 ccw(c51.206,39.878) 58.318,38.522 cw(c59.134,38.522) 58.557,39.098 58.842,39.383 cw(c59.722,38.502) 59.687,39.747 cw(c59.697,39.397) 59.748,39.743 ccw(c60.091,41.998) 60.787,39.826 ccw(c59.965,42.387) 61.868,40.486 62.727,41.345 cw(c63.98,40.092) 62.873,41.476 ; 46.087,44.997 cw(c51.206,39.878) 56.753,44.532 ; 46.406,35.276 cw(c51.206,39.878) 56.301,44.153 ; 46.626,43.861 cw(c51.206,39.878) 56.257,43.245 ; 46.702,36.775 ccw(c51.206,39.878) 56.649,40.426 ; 47.025,36.352 cw(c51.206,39.878) 55.865,42.745 ; 48.225,45.165 ccw(c51.206,39.878) 57.275,39.771 ; 55.865,42.746 ccw(c56.772,43.653) 56.772,42.37 58.691,42.37 ccw(c58.691,44.91) 60.487,43.114 61.44,44.066 cw(c62.194,43.312) 62.194,44.379 62.281,44.379 cw(c62.281,44.049) 62.611,44.049 62.611,43.416 cw(c62.281,43.416) 62.515,43.183 ; 56.256,43.246 ccw(c56.967,43.957) 56.257,43.245 ; 56.299,44.155 ccw(c57.765,45.621) 57.765,43.548 58.095,43.548 ccw(c58.095,45.976) 59.812,44.26 60.544,44.991 cw(c62.34,43.195) 62.337,45.735 ; 56.647,40.427 56.647,40.556 cw(c57.566,40.556) 56.916,41.206 cw(c58.063,40.06) 58.063,41.681 59.279,41.681 ccw(c59.279,43.225) 60.371,42.134 ; 56.751,44.534 56.771,44.514 ccw(c57.704,45.446) 57.704,44.127 57.848,44.127 ccw(c57.848,46.667) 59.644,44.871 60.363,45.591 cw(c62.159,43.795) 62.159,46.335 62.278,46.335 cw(c62.278,43.795) 64.074,45.591 64.204,45.461 cw(c63.339,44.596) 64.562,44.596 64.562,43.092 cw(c62.022,43.092) 63.818,41.296 63.505,40.983 ; 57.274,39.771 cw(c58.593,39.771) 57.661,40.704 57.777,40.82 cw(c58.286,40.311) 58.286,41.031 59.324,41.031 ccw(c59.324,43.571) 61.12,41.775 62.01,42.666 62.01,42.668 62.502,43.16 ; 57.838,39.309 57.838,39.589 cw(c58.688,39.589) 58.087,40.19 cw(c58.467,39.81) 58.467,40.348 59.598,40.348 ccw(c59.598,42.888) 61.394,41.092 62.626,42.324 ccw(c61.246,43.704) 63.198,43.704 63.198,44.145 ccw(c62.296,44.145) 62.934,44.783 ccw(c62.216,44.065) 62.216,45.08 62.194,45.08 ccw(c62.195,43.606) 61.153,44.648 60.124,43.619 cw(c58.512,45.231) 58.512,42.951 56.967,42.951 cw(c56.967,43.957) 56.257,43.245 ; 58.788,38.009 59.582,38.802 cw(c59.959,38.425) 59.959,38.959 ; 59.974,38.959 59.975,38.959 ccw(c59.975,42.599) 62.55,40.025 63.517,40.992 ; 60.373,42.136 61.662,43.425 cw(c61.979,43.108) v3@61.979,43.556 ; 62.34,45.735 ccw(c62.34,43.195) 62.337,45.735 ; 62.87,41.473 62.873,41.476 ; 62.337,45.735 cw(c62.337,44.356) 63.312,45.331 63.619,45.024 cw(c63.043,44.448) 63.858,44.448 63.858,43.241 cw(c61.976,43.241) 63.307,41.91 62.873,41.476
  other v1: 71.12,46.685 71.882,46.685 73.508,46.685 74.219,46.685
  other v3: 61.961,43.569 61.933,46.952
NetC1_1: C1.1 R1.2 | length 1.9
  Top Layer 1 w0.635: C1.1 67.691,29.21 R1.2@67.716,29.185
NetC1_2: C1.2 D1.2
NetC7_1: C7.1 FB1.1 pad.1@31.064,52.882
NetC8_1: C8.1 FB1.2 L1.1
NetC11_1: C11.1 R4.2 | length 2.3
  Top Layer 1 w0.635: C11.1@65.989,41.834 66.104,41.719 R4.2
NetC11_2: C11.2 D4.2
NetC12_1: C12.1 R3.1 | length 1.6
  Bottom Layer 1 w0.508: C12.1 R3.1
NetC18_1: C18.1 R9.2 | length 2.4
  Top Layer 1 w0.635: C18.1 68.986,47.447 R9.2@69.24,47.193
NetC18_2: C18.2 D7.2
NetD3_1: D3.1 D5.1 | length 3.2
  Bottom Layer 1 w0.635: D5.1 34.75,29.312 36.95,29.312 D3.1@37.49,29.852
NetR7_1: R7.1 R11.2 U1.7 | length 5.4
  Top Layer 1 w0.305: R11.2@26.774,33.505 26.825,33.556 26.825,34.456 ; R7.1 26.825,34.456 ; U1.7 27.331,34.456 26.825,34.456
NetR7_2: R7.2 U1.6 | length 2.1
  Top Layer 1 w0.305: R7.2@28.189,35.334 28.267,35.256 U1.6
PGND: C6.2 C7.2 C8.2 C9.2 C19.2 C25.2 C26.2 pad.1@27.348,52.882 R10.1 R11.1 U1.8 U1.9@32.146,34.856 | length 2.2
  Bottom Layer 1 w0.508: v5(32.146,36.106) R10.1@32.146,38.09 ; R10.1@32.146,37.836 R10.1@32.283,37.973
  other v2: 28.194,26.604 31.097,26.604 34,26.604 36.903,26.604 39.805,26.604 42.708,26.604 45.611,26.604 48.514,26.604 26.924,27.94 26.924,29.718 26.924,31.496 39.472,47.219 39.472,49.2 39.472,51.181 40.107,53.492 42.088,53.492 44.069,53.492 46.05,53.492 48.031,53.492
  other v5: 32.146,33.606 31.406,34.856 32.886,34.856
SS: C19.1 U1.5 | length 2.6
  Top Layer 1 w0.305: C19.1@28.463,37.005 28.666,37.005 28.987,36.685 ; C19.1@28.636,36.883 28.636,36.822 28.773,36.685 28.987,36.685 ; U1.5 29.616,36.056 28.987,36.685
SW: C12.2 D5.2 R8.1 U1.1
  other v1: 34.036,31.623 34.036,32.347 34.036,33.02
VIN: C6.1 C9.1 C26.1 D3.2 L1.2 R3.2 R6.2 U1.3 | length 469.4
  Top Layer 1 w0.8: v2@37.084,36.83 v2@37.262,36.652 ; v2(37.16,36.728) 37.16,36.139 ccw(c38.374,36.139) 37.516,35.281 38.65,34.146 ccw(c40.081,35.577) 40.081,33.553 41.419,33.553 ccw(c41.419,35.66) 42.908,34.17 43.586,34.848 cw(c44.323,34.111) 44.323,35.154 44.47,35.154 cw(c44.47,34.046) 45.253,34.829 ccw(c51.208,39.867) 44.304,43.497 42.926,41.681 42.834,41.59 cw(c41.707,42.717) 41.707,41.123 41.514,41.123 ccw(c41.514,38.583) 39.718,40.379 39.243,39.903 ccw(c40.347,38.8) 38.786,38.8 38.786,36.917 ccw(c41.326,36.917) 39.53,35.121 39.599,35.052 ccw(c40.343,35.797) 40.343,34.744 41.032,34.744 ccw(c41.032,37.161) 42.741,35.452 42.901,35.611 cw(c44.372,34.139) 44.372,36.22 44.501,36.22 cw(c44.501,34.026) 46.052,35.578 46.164,35.466 ccw(c51.206,39.878) 44.975,42.339 ; 40.288,36.242 40.208,36.322 ; v4(41.718,38.686) 42.48,38.686 ccw(c42.48,41.226) 44.276,39.43 45.695,40.848 cw(c51.208,39.867) 46.854,36.345 46.591,36.609 ccw(c44.966,34.984) 44.966,37.282 43.496,37.282 ccw(c43.496,36.26) 42.774,36.982 42.009,36.218 cw(c41.402,36.825) 41.402,35.966 41.067,35.966 cw(c41.067,37.18) 40.208,36.322 ; 44.975,42.339 43.358,40.462 cw(c42.07,41.75) 42.07,39.929 ccw(c42.07,37.764) 40.539,39.295 40.386,39.141 ccw(c41.49,38.038) 39.929,38.038 39.929,36.997 ccw(c40.883,36.997) 40.208,36.322
  Layer 2 w0.8: v2@37.084,36.83 v2@37.262,36.652 ; v2(37.16,36.728) 37.16,36.139 ccw(c38.374,36.139) 37.516,35.281 38.65,34.146 ccw(c40.081,35.577) 40.081,33.553 41.419,33.553 ccw(c41.419,35.66) 42.908,34.17 43.586,34.848 cw(c44.323,34.111) 44.323,35.154 44.47,35.154 cw(c44.47,34.046) 45.253,34.829 ccw(c51.208,39.867) 44.304,43.497 42.926,41.681 42.834,41.59 cw(c41.707,42.717) 41.707,41.123 41.514,41.123 ccw(c41.514,38.583) 39.718,40.379 39.243,39.903 ccw(c40.347,38.8) 38.786,38.8 38.786,36.917 ccw(c41.326,36.917) 39.53,35.121 39.599,35.052 ccw(c40.343,35.797) 40.343,34.744 41.032,34.744 ccw(c41.032,37.161) 42.741,35.452 42.901,35.611 cw(c44.372,34.139) 44.372,36.22 44.501,36.22 cw(c44.501,34.026) 46.052,35.578 46.164,35.466 ccw(c51.206,39.878) 44.975,42.339 ; 40.288,36.242 40.208,36.322 ; v4(41.718,38.686) 42.48,38.686 ccw(c42.48,41.226) 44.276,39.43 45.695,40.848 cw(c51.208,39.867) 46.854,36.345 46.591,36.609 ccw(c44.966,34.984) 44.966,37.282 43.496,37.282 ccw(c43.496,36.26) 42.774,36.982 42.009,36.218 cw(c41.402,36.825) 41.402,35.966 41.067,35.966 cw(c41.067,37.18) 40.208,36.322 ; 44.975,42.339 43.358,40.462 cw(c42.07,41.75) 42.07,39.929 ccw(c42.07,37.764) 40.539,39.295 40.386,39.141 ccw(c41.49,38.038) 39.929,38.038 39.929,36.997 ccw(c40.883,36.997) 40.208,36.322
  Bottom Layer 1 w0.508: R6.2@36.977,38.059 R6.2@37.236,37.8 ; v2@37.236,36.703 37.209,36.731 37.209,37.049 37.236,37.076 R6.2@37.236,37.8 ; R6.2@37.236,38.054 R6.2@37.236,37.8
  Bottom Layer 1 w0.8: v2@37.084,36.83 v2@37.262,36.652 ; v2(37.16,36.728) 37.16,36.139 ccw(c38.374,36.139) 37.516,35.281 38.116,34.68 38.218,34.579 38.65,34.146 ccw(c40.081,35.577) 40.081,33.553 41.419,33.553 ccw(c41.419,35.66) 42.908,34.17 43.586,34.848 cw(c44.323,34.111) 44.323,35.154 44.47,35.154 cw(c44.47,34.046) 45.253,34.829 ccw(c51.208,39.867) 44.304,43.497 42.926,41.681 42.834,41.59 cw(c41.707,42.717) 41.707,41.123 41.514,41.123 ccw(c41.514,38.583) 39.718,40.379 39.243,39.903 ccw(c40.347,38.8) 38.786,38.8 38.786,36.917 ccw(c41.326,36.917) 39.53,35.121 39.599,35.052 ccw(c40.343,35.797) 40.343,34.744 41.032,34.744 ccw(c41.032,37.161) 42.741,35.452 42.901,35.611 cw(c44.372,34.139) 44.372,36.22 44.501,36.22 cw(c44.501,34.026) 46.052,35.578 46.164,35.466 ccw(c51.206,39.878) 44.975,42.339 ; 40.288,36.242 40.208,36.322 ; v4(41.718,38.686) 42.48,38.686 ccw(c42.48,41.226) 44.276,39.43 45.695,40.848 cw(c51.208,39.867) 46.854,36.345 46.591,36.609 ccw(c44.966,34.984) 44.966,37.282 43.496,37.282 ccw(c43.496,36.26) 42.774,36.982 42.009,36.218 cw(c41.402,36.825) 41.402,35.966 41.067,35.966 cw(c41.067,37.18) 40.208,36.322 ; 44.975,42.339 43.358,40.462 cw(c42.07,41.75) 42.07,39.929 ccw(c42.07,37.764) 40.539,39.295 40.386,39.141 ccw(c41.49,38.038) 39.929,38.038 39.929,36.997 ccw(c40.883,36.997) 40.208,36.322
  other v2: 37.186,35.763 36.257,35.815 36.257,36.68
  other v4: 41.067,37.18 41.885,37.694 41.035,38.042
VOUT1: C2.1 C3.1 C4.1 C5.1 C10.1 D1.1 D2.1 J2.1 R1.1 R2.2
  other v1: 71.196,30.251 71.958,30.251 73.584,30.251 74.295,30.251
VOUT2: C13.1 C14.1 C15.1 C16.1 C17.1 D4.1 D6.1 J3.1 R4.1 R5.2 | length 3
  Top Layer 1 w0.635: 68.199,37.084 R4.1
  other v1: 71.145,36.855 71.907,36.855 73.533,36.855 74.244,36.855
VOUT3: C20.1 C21.1 C22.1 C23.1 C24.1 D7.1 D8.1 J4.1 R9.1 R12.2
  other v1: 71.12,45.187 71.882,45.187 73.508,45.187 74.219,45.187
pads on no net: U1.9@32.146,34.101 U1.9@32.146,35.611

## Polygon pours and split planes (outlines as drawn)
PGND on Top Layer 1 "PGND_L01_P033" (solid, pour order 33): 26.187,53.594 26.543,53.95 29.058,53.95 29.566,53.442 29.566,48.209 30.328,47.447 33.096,47.447 33.325,47.219 33.325,44.983 33.299,44.958 33.299,33.731 35.408,31.623 43.129,31.623 43.307,31.445 43.307,29.108 43.637,28.778 50.597,28.778 50.927,28.448 50.927,26.391 50.698,26.162 26.441,26.162 26.187,26.416
PGND on Top Layer 1 "PGND_L01_P066" (solid, pour order 66): 43.524,44.671 43.524,50.705 43.721,50.902 48.489,50.902 48.793,51.206 48.793,53.67 48.387,54.077 39.268,54.077 38.456,53.264 38.456,44.348 37.109,43.002 37.109,41.707 37.846,40.97 39.091,40.97 40.06,41.939 cw(c40.97,41.029) 40.97,42.316 ccw(c40.97,43.42) 41.751,42.64 43.006,43.895 ccw(c41.315,45.586)
NetC7_1 on Top Layer 1 "NETC7_1_L01_P024" (solid, pour order 24): 33.604,50.368 33.757,50.521 33.757,53.213 33.071,53.899 30.531,53.899 30.074,53.442 30.074,50.521 30.226,50.368
NetC8_1 on Top Layer 1 "NETC8_1_L01_P025" (solid, pour order 25): 34.341,51.537 34.417,51.613 36.17,51.613 36.601,51.181 37.973,49.809 37.973,48.59 37.694,48.311 31.75,48.311 31.598,48.463 31.598,49.784 31.75,49.936 33.782,49.936 34.341,50.495
GND1 on Top Layer 1 "GND1_L01_P065" (solid, pour order 65): 52.349,28.448 52.603,28.702 61.62,28.702 62.509,27.813 81.178,27.813 81.559,27.432 81.559,26.289 81.305,26.035 52.857,26.035 52.349,26.543
VOUT3 on Top Layer 1 "VOUT3_L01_P064" (solid, pour order 64): 81.382,45.644 81.509,45.517 81.509,43.917 81.255,43.663 67.031,43.663 66.497,44.196 66.497,45.644 67.056,46.203 70.028,46.203 70.587,45.644
VOUT1 on Top Layer 1 "VOUT1_L01_P063" (solid, pour order 63): 67.945,30.759 68.758,29.947 68.758,28.524 69.317,27.965 81.331,27.965 81.661,28.296 81.661,30.328 81.305,30.683 70.51,30.683 68.961,32.233 66.548,32.233 66.446,32.131 66.446,30.836 66.523,30.759
VOUT2 on Top Layer 1 "VOUT2_L01_P037" (solid, pour order 37): 81.204,38.379 81.534,38.049 81.534,35.56 81.153,35.179 68.428,35.179 67.869,35.738 67.869,37.871 70.282,37.871 70.968,37.186 78.892,37.186 80.086,38.379
SW on Top Layer 1 "SW_L01_P031" (solid, pour order 31): 34.442,33.884 34.519,33.807 34.519,33.503 34.823,33.198 36.017,33.198 36.22,32.995 36.22,31.318 36.119,31.217 33.858,31.217 33.68,31.394 33.68,33.782 33.782,33.884
VIN on Top Layer 1 "VIN_L01_P029" (solid, pour order 29): 37.871,47.523 38.049,47.346 38.049,44.628 36.754,43.332 36.754,42.672 36.754,40.818 37.668,39.903 37.668,35.154 37.592,35.077 33.757,35.077 33.706,35.128 33.706,42.951 33.325,43.332 30.723,43.332 30.658,43.398 30.658,45.208 30.764,45.314 33.172,45.314 33.757,45.898 33.757,47.313 33.967,47.523
PGND on Bottom Layer 1 "PGND_L06_P069" (solid, pour order 69): 37.795,45.7 38.526,46.431 38.633,46.431 38.633,53.289 39.421,54.077 48.514,54.077 48.87,53.721 48.87,51.029 48.666,50.825 43.282,50.825 42.951,50.495 42.951,45.517 41.763,44.328 41.763,34.524 43.236,33.051 43.236,28.936 43.49,28.682 50.602,28.682 50.856,28.428 50.856,26.269 50.602,26.015 26.244,26.015 25.99,26.269 25.99,44.811 26.879,45.7
VIN on Bottom Layer 1 "VIN_L06_P060" (solid, pour order 60): 35.865,35.433 36.398,34.9 36.398,32.842 36.576,32.664 38.43,32.664 38.744,32.979 38.744,34.56 37.821,35.484 37.668,35.484 37.668,37.363 37.77,37.465 37.77,38.633 37.617,38.786 36.906,38.786 36.728,38.608 36.728,37.49 36.347,37.109 34.976,37.109 34.696,36.83 34.696,35.458 34.722,35.433
SW on Bottom Layer 1 "SW_L06_P059" (solid, pour order 59): 30.836,30.328 30.836,28.778 31.191,28.423 32.385,28.423 32.537,28.575 32.537,29.718 33.452,30.607 35.56,30.607 35.687,30.734 35.687,31.75 35.56,31.877 34.569,31.877 34.29,32.156 34.29,33.274 34.163,33.401 33.909,33.401
VOUT3 on Bottom Layer 1 "VOUT3_L06_P036" (solid, pour order 36): 81.483,45.644 81.661,45.466 81.661,43.383 81.128,42.85 70.917,42.85 70.587,43.18 70.587,45.187 71.044,45.644
VOUT2 on Bottom Layer 1 "VOUT2_L06_P035" (solid, pour order 35): 78.562,37.592 79.273,38.303 81.432,38.303 81.661,38.075 81.661,37.414 81.661,35.458 81.001,34.798 70.79,34.798 70.46,35.128 70.46,37.135 70.917,37.592
VOUT1 on Bottom Layer 1 "VOUT1_L06_P034" (solid, pour order 34): 80.874,28.016 81.534,28.677 81.534,30.632 81.356,30.81 70.79,30.81 70.333,30.353 70.333,28.346 70.663,28.016
PGND on Layer 1 "PGND_L02_P038" (solid, pour order 38): 38.608,53.264 39.37,54.026 48.514,54.026 48.87,53.67 48.87,50.952 41.834,43.917 41.834,34.544 43.307,33.071 43.307,28.956 43.561,28.702 50.673,28.702 50.927,28.448 50.927,26.289 50.673,26.035 26.314,26.035 26.06,26.289 26.06,44.831 26.949,45.72 37.795,45.72 38.608,46.533
GND2 on Layer 1 "GND2_L02_P054" (solid, pour order 54): 68.072,35.814 67.691,36.195 67.691,41.402 68.072,41.783 81.153,41.783 81.788,41.148 81.788,35.814
GND3 on Layer 1 "GND3_L02_P048" (solid, pour order 48): 81.407,45.593 80.264,44.45 60.706,44.45 59.817,45.339 59.817,51.562 60.96,52.705 80.899,52.705 81.407,52.197
GND1 on Layer 1 "GND1_L02_P046" (solid, pour order 46): 52.832,25.908 81.28,25.908 81.788,26.416 81.788,32.893 81.153,33.528 67.183,33.528 64.516,30.861 59.817,30.861 59.563,30.607 59.563,29.083 58.928,28.448 52.578,28.448 52.324,28.194 52.324,26.416
GND2 on Top Layer "GND2_L03_P053" (solid, pour order 53): 81.788,35.814 81.788,41.148 81.153,41.783 70.104,41.783 69.088,40.767 69.088,36.068 69.342,35.814
GND3 on Top Layer "GND3_L03_P051" (solid, pour order 51): 81.661,45.847 80.264,44.45 60.706,44.45 59.817,45.339 59.817,51.562 60.96,52.705 80.899,52.705 81.661,51.943
GND1 on Top Layer "GND1_L03_P047" (solid, pour order 47): 52.832,25.908 81.28,25.908 81.788,26.416 81.788,32.893 80.899,33.782 64.262,33.782 61.341,30.861 59.563,29.083 58.928,28.448 52.578,28.448 52.324,28.194 52.324,26.416
PGND on Top Layer "PGND_L03_P042" (solid, pour order 42): 37.795,45.7 38.526,46.431 38.633,46.431 38.633,53.289 39.421,54.077 48.514,54.077 48.87,53.721 48.87,51.029 48.666,50.825 43.282,50.825 42.951,50.495 42.951,45.517 41.763,44.328 41.763,34.524 43.236,33.051 43.236,28.936 43.49,28.682 50.602,28.682 50.856,28.428 50.856,26.269 50.602,26.015 26.244,26.015 25.99,26.269 25.99,44.811 26.879,45.7
PGND on Bottom Layer "PGND_L04_P067" (solid, pour order 67): 37.795,45.7 38.526,46.431 38.633,46.431 38.633,53.289 39.421,54.077 48.514,54.077 48.87,53.721 48.87,51.029 48.666,50.825 43.282,50.825 42.951,50.495 42.951,45.517 41.763,44.328 41.763,34.524 43.236,33.051 43.236,28.936 43.49,28.682 50.602,28.682 50.856,28.428 50.856,26.269 50.602,26.015 26.244,26.015 25.99,26.269 25.99,44.811 26.879,45.7
GND2 on Bottom Layer "GND2_L04_P058" (solid, pour order 58): 68.072,35.814 67.691,36.195 67.691,41.402 68.072,41.783 81.153,41.783 81.788,41.148 81.788,35.814
GND3 on Bottom Layer "GND3_L04_P057" (solid, pour order 57): 65.278,52.705 64.262,51.689 64.262,47.498 67.31,44.45 80.264,44.45 81.407,45.593 81.407,52.197 80.899,52.705
GND1 on Bottom Layer "GND1_L04_P049" (solid, pour order 49): 52.832,25.908 81.28,25.908 81.788,26.416 81.788,32.893 80.899,33.782 64.262,33.782 61.341,30.861 59.563,29.083 58.928,28.448 52.578,28.448 52.324,28.194 52.324,26.416
PGND on Layer 2 "PGND_L05_P068" (solid, pour order 68): 37.795,45.7 38.526,46.431 38.633,46.431 38.633,53.289 39.421,54.077 48.514,54.077 48.87,53.721 48.87,51.029 48.666,50.825 43.282,50.825 42.951,50.495 42.951,45.517 41.763,44.328 41.763,34.524 43.236,33.051 43.236,28.936 43.49,28.682 50.602,28.682 50.856,28.428 50.856,26.269 50.602,26.015 26.244,26.015 25.99,26.269 25.99,44.811 26.879,45.7
GND2 on Layer 2 "GND2_L05_P062" (solid, pour order 62): 68.072,35.814 67.691,36.195 67.691,41.402 68.072,41.783 81.153,41.783 81.788,41.148 81.788,35.814
GND3 on Layer 2 "GND3_L05_P052" (solid, pour order 52): 81.661,45.969 80.053,44.361 60.495,44.361 59.606,45.25 59.606,51.473 60.749,52.616 80.688,52.616 81.661,51.643
GND1 on Layer 2 "GND1_L05_P050" (solid, pour order 50): 52.832,25.908 81.28,25.908 81.788,26.416 81.788,32.893 80.899,33.782 64.262,33.782 61.976,31.496 59.563,29.083 58.928,28.448 52.578,28.448 52.324,28.194 52.324,26.416

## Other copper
Top Layer 1:
  region net VIN: 42.24,37.998 42.748,38.506 42.24,39.014 42.164,39.091 41.529,39.091 40.818,38.379 40.691,38.252 40.691,37.023 40.9,36.813 41.512,36.813 42.037,37.338 42.24,37.541
  region net NetC18_2: 61.646,43.18 63.932,43.18 65.634,44.882 65.634,48.285 65.456,48.463 64.237,48.463 63.83,48.057 63.83,46.05 61.544,43.764 61.544,43.282
  region net NetC1_2: 63.119,28.397 64.44,28.397 64.491,28.448 64.491,30.378 65.1,30.988 65.1,32.106 62.408,34.798 61.671,34.798 61.544,34.671 61.544,33.477 63.119,31.902 63.119,28.397
  region net NetC11_2: 65.557,36.424 66.954,36.424 67.081,36.551 67.081,40.589 67.005,40.665 65.43,40.665 65.329,40.564 65.329,36.652
  region net GND2: 71.425,37.567 76.175,37.567 78.765,37.567 79.908,38.71 81.509,38.71 81.686,38.887 81.686,40.183 81.178,40.691 70.079,40.691 69.698,40.31 69.698,39.294
  region net GND1: 69.875,33.909 70.333,33.452 81.356,33.452 81.534,33.274 81.534,31.267 81.178,30.912 71.018,30.912 69.088,32.842 65.481,32.842 65.126,33.198 65.126,33.757 65.278,33.909
  region net GND3: 71.196,45.898 81.28,45.898 81.559,46.177 81.559,52.197 81.051,52.705 60.681,52.705 59.715,51.74 59.715,47.193 60.579,46.33 62.941,46.33 63.246,46.634 63.246,48.489 63.678,48.92 69.723,48.92 70.688,47.955 70.688,46.406
Top Layer:
  region net SW: 40.54,37.197 40.54,38.736 41.073,39.27 41.781,39.27 42.189,38.862 42.189,34.925 38.379,31.115 34.061,31.115 33.807,31.369 33.807,33.02 34.061,33.274 36.617,33.274
Layer 2:
  region net VIN: 35.919,35.255 37.338,35.255 37.643,35.56 37.643,36.881 37.122,37.401 36.08,37.401 35.622,36.943 35.622,35.552
  region net VIN: 42.24,37.998 42.748,38.506 42.24,39.014 42.164,39.091 41.529,39.091 40.818,38.379 40.691,38.252 40.691,37.023 40.9,36.813 41.512,36.813 42.037,37.338 42.24,37.541
Bottom Layer 1:
  region net VIN: 42.24,37.998 42.748,38.506 42.24,39.014 42.164,39.091 41.529,39.091 40.818,38.379 40.691,38.252 40.691,37.023 40.9,36.813 41.512,36.813 42.037,37.338 42.24,37.541
  pour cut-out: 35.687,32.436 36.938,32.436 37.151,32.648 38.744,32.648 38.744,28.407 38.532,28.194 32.842,28.194 32.842,29.312 33.96,30.429 35.641,30.429 35.687,30.475
  region net GND2: 78.054,37.948 78.791,38.684 81.331,38.684 81.712,39.065 81.712,40.869 81.432,41.148 70.104,41.148 69.596,40.64 69.596,38.278 69.926,37.948
  region net GND1: 62.484,32.868 63.525,33.909 65.278,33.909 69.875,33.909 70.333,33.452 81.356,33.452 81.534,33.274 81.534,31.267 81.178,30.912 70.129,30.912 70.053,30.912 69.748,30.607 69.748,27.94 70.002,27.686 81.051,27.686 81.559,27.178 81.559,26.162 81.432,26.035 52.476,26.035 52.095,26.416 52.095,28.003 52.768,28.677 59.157,28.677 59.919,29.439 59.919,32.309 60.477,32.868
  region net GND3: 71.196,45.898 81.28,45.898 81.559,46.177 81.559,52.197 81.051,52.705 60.681,52.705 59.715,51.74 59.715,47.193 61.011,45.898

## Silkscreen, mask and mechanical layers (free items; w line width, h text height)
Top Overlay:
  circle w0.1: c51.206,39.878 r4.4
  lines w0.1: 44.501,33.875 ccw(c51.206,39.878) 57.911,33.874 ; 47.296,37.889 44.497,33.869 44.206,33.578 44.206,29.628 58.206,29.628 58.206,33.578 57.916,33.869 55.117,37.861 55.106,37.878 ; 47.296,41.895 44.502,45.882 cw(c51.206,39.878) 57.912,45.881 ; 55.117,41.895 57.916,45.887 58.206,46.178 58.206,50.128 44.206,50.128 44.206,46.178 44.506,45.878 ; 44.506,45.878 44.506,45.878
  text "VBAT" at 33.096,52.68 h1.02
  text "GND" at 25.984,51.714 h1.02 r270
  text "-" at 80.239,48.87 h1.02
  text "+" at 80.264,42.096 h1.02
  text "-" at 80.315,40.818 h1.02
  text "+" at 80.315,34.375 h1.02
  text "-" at 80.315,33.579 h1.02
  text "+" at 80.391,27.11 h1.02
Bottom Overlay:
  circle w0.1: c51.206,39.878 r4.4
  lines w0.1: 44.501,33.875 ccw(c51.206,39.878) 57.911,33.874 ; 47.296,37.889 44.497,33.869 44.206,33.578 44.206,29.628 58.206,29.628 58.206,33.578 57.916,33.869 55.117,37.861 55.106,37.878 ; 47.296,41.895 44.502,45.882 cw(c51.206,39.878) 57.912,45.881 ; 55.117,41.895 57.916,45.887 58.206,46.178 58.206,50.128 44.206,50.128 44.206,46.178 44.506,45.878 ; 44.506,45.878 44.506,45.878
Mechanical 1:
  circle w0.1: c51.206,39.878 r4.8
  lines w0.1: 44.29,34.364 43.706,33.778 43.706,29.128 58.706,29.128 58.706,33.778 58.115,34.366 57.683,34.366 ; 44.298,34.366 44.729,34.366 ; 44.298,45.39 44.729,45.39 ; 44.298,45.392 43.706,45.978 43.706,50.628 58.706,50.628 58.706,45.978 58.13,45.392 ; 44.736,45.39 cw(c51.206,39.878) 57.678,45.389 ; 44.74,34.361 ccw(c51.206,39.878) 57.68,34.369 ; 57.683,45.39 58.115,45.39
  lines w0.254: 25.527,25.527 82.321,25.527 82.321,54.432 25.527,54.432 25.527,25.527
